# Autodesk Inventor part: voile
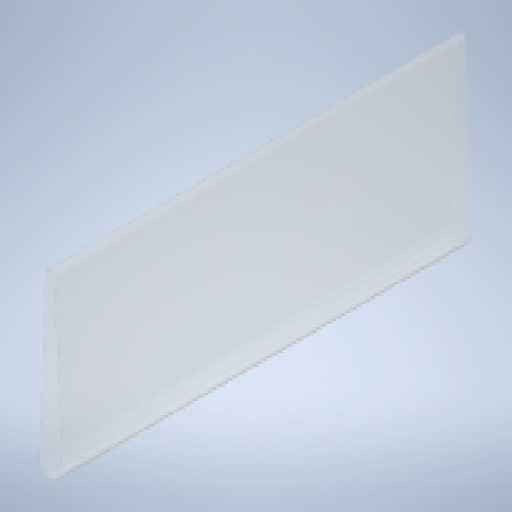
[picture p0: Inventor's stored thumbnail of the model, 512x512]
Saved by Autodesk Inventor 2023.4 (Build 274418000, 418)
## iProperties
Created: 2023-11
Part Number: voile
Material: Polycarbonate, transparent
Document SubType Name: Modeling
Designer: mel
Density: 1.2 g/cm^3
Appearance: Polycarbonate - Transparent
Author: mel
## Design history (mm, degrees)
sketch "Esquisse1"
  geometry: L1 (-1.998, 37.907)-(-4.996, -36.973); L2 (4.996, -36.973)-(1.998, 37.907); L3 (2.198, 37.915)-(5.196, -36.965); L4 (-5.196, -36.965)-(-2.198, 37.915); A1 r 2 centre (0, 37.827) between (1.998, 37.907) and (-1.998, 37.907); A2 r 5 centre (0, -37.173) between (-4.996, -36.973) and (4.996, -36.973); A3 r 5.2 centre (0, -37.173) between (-5.196, -36.965) and (5.196, -36.965); A4 r 2.2 centre (0, 37.827) between (2.198, 37.915) and (-2.198, 37.915); 1 further point
  constraints: 8 end point, 8 point on circle, 4 centre point, 3 other
  dimensions: "d0" = 0.2 distance between parallel lines of L2 L3
node "Plan de construction1"
extrude "Extrusion1" new body sketch "Esquisse1" stored distance "d1" = 10; taper "d2" = 0 deg
node "Solide1"
